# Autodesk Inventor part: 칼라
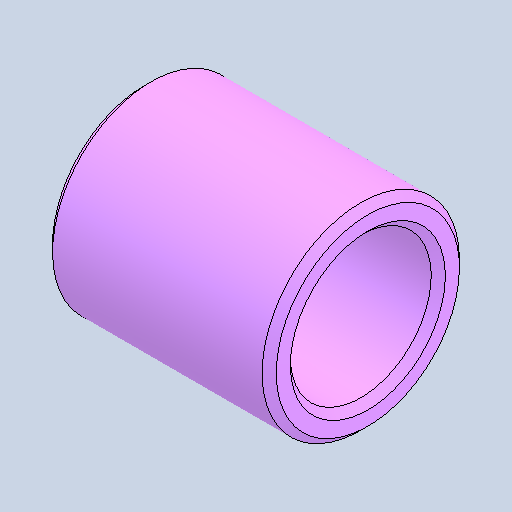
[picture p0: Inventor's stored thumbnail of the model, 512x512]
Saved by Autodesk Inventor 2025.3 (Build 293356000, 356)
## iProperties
Created: 2026-01
Part Number: 칼라
Material: 강철, 연강
Document SubType Name: Modeling
Designer: pc6
Density: 7.85 g/cm^3
Appearance: 기본값
Author: jhkim
Sending System: Autodesk Inventor 2026
Preprocessor: ST-DEVELOPER v20.1
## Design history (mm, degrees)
feature "솔리드1"
node "솔리드2"
